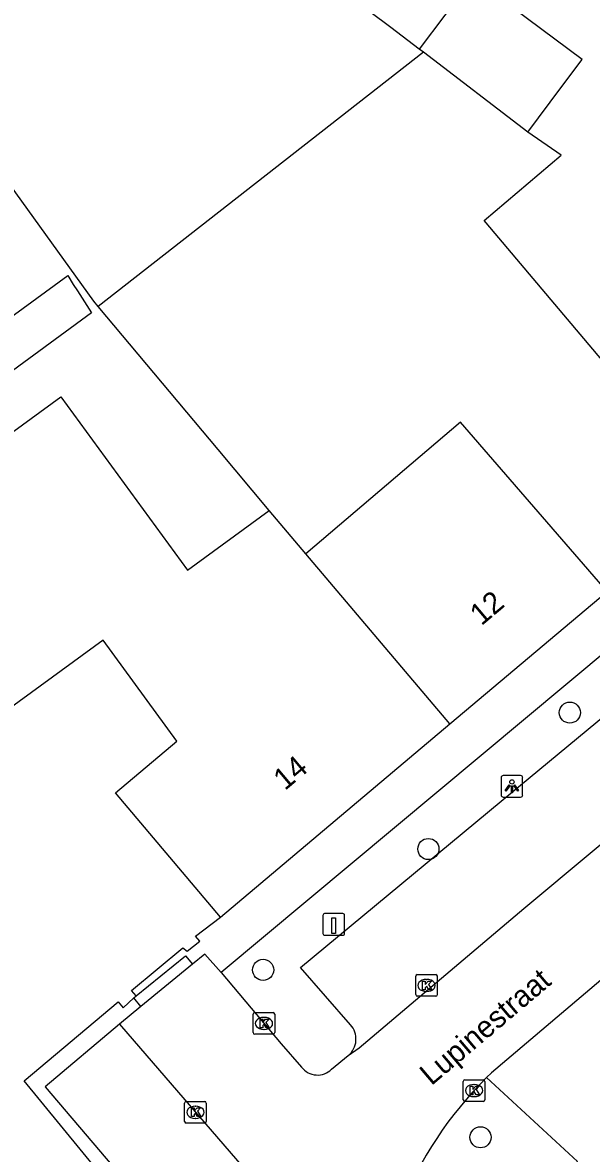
# Model space of a CAD drawing. Extents: x 161882 to 162509, y 381687 to 382379.
# Drawn here: x 162311.3 to 162337.7, y 381877.6 to 381930 of the extents above; entities that cross this region are included whole.
import ezdxf

# ---------------------------------------------------------------- set-up
doc = ezdxf.new("R2010")
doc.units = 0
for name, color, linetype in [('IMGEO_Boom', 7, 'Continuous'), ('IMGEO_Kolk', 7, 'Continuous'), ('IMGEO_Laadpaal', 7, 'Continuous'), ('IMGEO_Lichtpunt', 7, 'Continuous'), ('IMGEO_Openbare_ruimte_label', 7, 'Continuous'), ('IMGEO_Pand', 7, 'Continuous'), ('IMGEO_Pand_nummerreeks', 7, 'Continuous'), ('IMGEO_Parkeervlak_open', 7, 'Continuous'), ('IMGEO_Rijbaan_lokaal_open', 7, 'Continuous'), ('IMGEO_Voetpad_open', 7, 'Continuous')]:
    doc.layers.add(name, color=color, linetype=linetype)

msp = doc.modelspace()

# ---------------------------------------------------------------- linework, layer by layer
at = {"layer": 'IMGEO_Boom'}
for centre in [(162336.672, 381898.043), (162330.128, 381891.725), (162322.477, 381886.132), (162332.539, 381878.382)]:
    msp.add_circle(centre, 0.489, dxfattribs=at)
at = {"layer": 'IMGEO_Kolk'}
for p, q in [((162329.539, 381884.985), (162329.539, 381885.837)), ((162329.614, 381885.911), (162330.466, 381885.911)), ((162330.027, 381885.691), (162330.052, 381885.691)), ((162330.54, 381885.837), (162330.54, 381884.985)), ((162330.05, 381885.131), (162330.025, 381885.131)), ((162330.466, 381884.911), (162329.614, 381884.911)), ((162322.017, 381883.228), (162322.017, 381884.08)), ((162322.092, 381884.154), (162322.944, 381884.154)), ((162323.018, 381884.08), (162323.018, 381883.228)), ((162322.505, 381883.934), (162322.53, 381883.934)), ((162322.944, 381883.154), (162322.092, 381883.154)), ((162322.528, 381883.374), (162322.503, 381883.374)), ((162331.742, 381880.119), (162331.742, 381880.971)), ((162331.817, 381881.045), (162332.669, 381881.045)), ((162332.23, 381880.825), (162332.255, 381880.825)), ((162332.743, 381880.971), (162332.743, 381880.119)), ((162318.846, 381879.113), (162318.846, 381879.965)), ((162318.921, 381880.039), (162319.773, 381880.039)), ((162319.334, 381879.819), (162319.359, 381879.819)), ((162319.847, 381879.965), (162319.847, 381879.113)), ((162332.669, 381880.045), (162331.817, 381880.045)), ((162332.253, 381880.265), (162332.228, 381880.265)), ((162319.357, 381879.259), (162319.332, 381879.259)), ((162319.773, 381879.039), (162318.921, 381879.039))]:
    msp.add_line(p, q, dxfattribs=at)
for points in [[(162329.539, 381884.985), (162329.539, 381885.837)], [(162329.614, 381885.911), (162330.466, 381885.911)], [(162329.86, 381885.611), (162329.983, 381885.611), (162329.983, 381885.46), (162330.113, 381885.611), (162330.277, 381885.611), (162330.131, 381885.46), (162330.284, 381885.211), (162330.132, 381885.211), (162330.047, 381885.375), (162329.983, 381885.308), (162329.983, 381885.211), (162329.86, 381885.211), (162329.86, 381885.611)], [(162330.54, 381885.837), (162330.54, 381884.985)], [(162330.466, 381884.911), (162329.614, 381884.911)], [(162322.017, 381883.228), (162322.017, 381884.08)], [(162322.092, 381884.154), (162322.944, 381884.154)], [(162323.018, 381884.08), (162323.018, 381883.228)], [(162322.338, 381883.854), (162322.461, 381883.854), (162322.461, 381883.703), (162322.591, 381883.854), (162322.755, 381883.854), (162322.609, 381883.703), (162322.762, 381883.454), (162322.61, 381883.454), (162322.525, 381883.618), (162322.461, 381883.551), (162322.461, 381883.454), (162322.338, 381883.454), (162322.338, 381883.854)], [(162322.944, 381883.154), (162322.092, 381883.154)], [(162331.742, 381880.119), (162331.742, 381880.971)], [(162331.817, 381881.045), (162332.669, 381881.045)], [(162332.743, 381880.971), (162332.743, 381880.119)], [(162332.063, 381880.745), (162332.186, 381880.745), (162332.186, 381880.594), (162332.316, 381880.745), (162332.48, 381880.745), (162332.334, 381880.594), (162332.487, 381880.345), (162332.335, 381880.345), (162332.25, 381880.509), (162332.186, 381880.442), (162332.186, 381880.345), (162332.063, 381880.345), (162332.063, 381880.745)], [(162318.846, 381879.113), (162318.846, 381879.965)], [(162318.921, 381880.039), (162319.773, 381880.039)], [(162319.847, 381879.965), (162319.847, 381879.113)], [(162332.669, 381880.045), (162331.817, 381880.045)], [(162319.167, 381879.739), (162319.29, 381879.739), (162319.29, 381879.588), (162319.42, 381879.739), (162319.584, 381879.739), (162319.438, 381879.588), (162319.591, 381879.339), (162319.439, 381879.339), (162319.354, 381879.503), (162319.29, 381879.436), (162319.29, 381879.339), (162319.167, 381879.339), (162319.167, 381879.739)], [(162319.773, 381879.039), (162318.921, 381879.039)]]:
    msp.add_lwpolyline(points, dxfattribs=at)
for centre, start, end in [((162329.616, 381885.835), 91.552, 178.448), ((162329.616, 381885.835), 91.552, 178.448), ((162330.464, 381885.835), 1.552, 88.448), ((162330.464, 381885.835), 1.552, 88.448), ((162329.616, 381884.987), 181.552, 268.448), ((162329.616, 381884.987), 181.552, 268.448), ((162330.464, 381884.987), 271.552, 358.448), ((162330.464, 381884.987), 271.552, 358.448), ((162322.094, 381884.078), 91.552, 178.448), ((162322.094, 381884.078), 91.552, 178.448), ((162322.942, 381884.078), 1.552, 88.448), ((162322.942, 381884.078), 1.552, 88.448), ((162322.094, 381883.23), 181.552, 268.448), ((162322.094, 381883.23), 181.552, 268.448), ((162322.942, 381883.23), 271.552, 358.448), ((162322.942, 381883.23), 271.552, 358.448), ((162331.819, 381880.969), 91.552, 178.448), ((162331.819, 381880.969), 91.552, 178.448), ((162332.667, 381880.969), 1.552, 88.448), ((162332.667, 381880.969), 1.552, 88.448), ((162318.923, 381879.963), 91.552, 178.448), ((162318.923, 381879.963), 91.552, 178.448), ((162319.771, 381879.963), 1.552, 88.448), ((162319.771, 381879.963), 1.552, 88.448), ((162331.819, 381880.121), 181.552, 268.448), ((162331.819, 381880.121), 181.552, 268.448), ((162332.667, 381880.121), 271.552, 358.448), ((162332.667, 381880.121), 271.552, 358.448), ((162318.923, 381879.115), 181.552, 268.448), ((162318.923, 381879.115), 181.552, 268.448), ((162319.771, 381879.115), 271.552, 358.448), ((162319.771, 381879.115), 271.552, 358.448)]:
    msp.add_arc(centre, 0.0765, start, end, dxfattribs=at)
for centre, major_axis, ratio, start_param, end_param in [((162330.026, 381885.411), (-0.387, 0.002), 0.722429, 4.712389, 7.853982), ((162330.051, 381885.411), (-0.39, 0.002), 0.717154, 1.570796, 4.712389), ((162322.504, 381883.654), (-0.387, 0.002), 0.722429, 4.712389, 7.853982), ((162322.529, 381883.654), (-0.39, 0.002), 0.717154, 1.570796, 4.712389), ((162332.229, 381880.545), (-0.387, 0.002), 0.722429, 4.712389, 7.853982), ((162332.254, 381880.545), (-0.39, 0.002), 0.717154, 1.570796, 4.712389), ((162319.333, 381879.539), (-0.387, 0.002), 0.722429, 4.712389, 7.853982), ((162319.358, 381879.539), (-0.39, 0.002), 0.717154, 1.570796, 4.712389)]:
    msp.add_ellipse(centre, major_axis=major_axis, ratio=ratio, start_param=start_param, end_param=end_param, dxfattribs=at)
at = {"layer": 'IMGEO_Laadpaal'}
for p, q in [((162326.164, 381888.735), (162325.323, 381888.735)), ((162326.164, 381888.735), (162325.323, 381888.735)), ((162326.248, 381887.819), (162326.248, 381888.66)), ((162326.248, 381887.819), (162326.248, 381888.66)), ((162325.248, 381888.651), (162325.248, 381887.81)), ((162325.248, 381888.651), (162325.248, 381887.81)), ((162325.332, 381887.735), (162326.173, 381887.735)), ((162325.332, 381887.735), (162326.173, 381887.735))]:
    msp.add_line(p, q, dxfattribs=at)
msp.add_lwpolyline([(162325.663, 381888.548), (162325.823, 381888.548), (162325.823, 381887.815), (162325.663, 381887.815), (162325.663, 381888.548)], dxfattribs=at)
for centre, start, end in [((162325.326, 381888.657), 92.4484, 184.2845), ((162325.326, 381888.657), 92.4484, 184.2845), ((162326.17, 381888.657), 2.4484, 94.2845), ((162326.17, 381888.657), 2.4484, 94.2845), ((162325.326, 381887.813), 182.4484, 274.2845), ((162325.326, 381887.813), 182.4484, 274.2845), ((162326.17, 381887.813), 272.4484, 4.2845), ((162326.17, 381887.813), 272.4484, 4.2845)]:
    msp.add_arc(centre, 0.0779, start, end, dxfattribs=at)
at = {"layer": 'IMGEO_Lichtpunt'}
for p, q in [((162333.493, 381895.033), (162333.493, 381894.226)), ((162333.493, 381895.033), (162333.493, 381894.226)), ((162334.395, 381895.128), (162333.587, 381895.128)), ((162334.395, 381895.128), (162333.587, 381895.128)), ((162334.489, 381894.226), (162334.489, 381895.033)), ((162334.489, 381894.226), (162334.489, 381895.033)), ((162333.587, 381894.132), (162334.395, 381894.132)), ((162333.587, 381894.132), (162334.395, 381894.132))]:
    msp.add_line(p, q, dxfattribs=at)
for points in [[(162333.867, 381894.697), (162333.906, 381894.669), (162333.718, 381894.407), (162333.68, 381894.434), (162333.867, 381894.697)], [(162333.969, 381894.649), (162334.016, 381894.649), (162334.016, 381894.327), (162333.969, 381894.327), (162333.969, 381894.649)], [(162334.079, 381894.669), (162334.117, 381894.696), (162334.304, 381894.434), (162334.265, 381894.406), (162334.079, 381894.669)]]:
    msp.add_lwpolyline(points, dxfattribs=at)
msp.add_circle((162333.992, 381894.831), 0.0994, dxfattribs=at)
for centre, start, end in [((162333.587, 381895.033), 90, 180), ((162333.587, 381895.033), 90, 180), ((162334.395, 381895.033), 0, 90), ((162334.395, 381895.033), 0, 90), ((162333.587, 381894.226), 180, 270), ((162333.587, 381894.226), 180, 270), ((162334.395, 381894.226), 270, 0), ((162334.395, 381894.226), 270, 360)]:
    msp.add_arc(centre, 0.0946, start, end, dxfattribs=at)
at = {"layer": 'IMGEO_Pand'}
for points in [[(162329.705, 381928.752), (162328.389, 381929.759), (162322.559, 381934.122), (162315.708, 381939.25), (162314.837, 381938.086), (162316.301, 381936.99), (162316.88, 381936.187), (162312.352, 381932.924)], [(162334.722, 381924.911), (162336.256, 381926.959), (162337.238, 381928.272), (162332.18, 381932.056), (162330.883, 381930.326), (162329.705, 381928.752)], [(162329.893, 381928.608), (162314.839, 381916.848)], [(162329.893, 381928.608), (162329.705, 381928.752)], [(162334.722, 381924.911), (162329.893, 381928.608)], [(162314.839, 381916.848), (162314.64, 381917.085), (162309.637, 381924.029), (162306.732, 381928.061)], [(162343.439, 381908.114), (162340.325, 381911.802), (162332.799, 381920.714), (162332.702, 381920.828), (162336.276, 381923.854), (162334.722, 381924.911)], [(162307.853, 381914.196), (162313.435, 381918.272), (162313.691, 381917.867), (162313.882, 381917.565), (162314.529, 381916.542), (162308.947, 381912.466)], [(162322.762, 381907.393), (162320.397, 381910.215), (162314.839, 381916.848)], [(162320.508, 381888.575), (162315.645, 381894.334), (162318.477, 381896.725), (162315.068, 381901.394), (162281.55, 381876.921), (162275.507, 381885.197), (162313.123, 381912.663), (162318.985, 381904.635), (162322.762, 381907.393)], [(162338.405, 381903.648), (162331.614, 381911.491), (162324.457, 381905.392)], [(162324.457, 381905.392), (162322.762, 381907.393)], [(162331.126, 381897.517), (162324.457, 381905.392)], [(162331.126, 381897.517), (162338.405, 381903.648)], [(162320.508, 381888.575), (162331.126, 381897.517)]]:
    msp.add_lwpolyline(points, dxfattribs=at)
at = {"layer": 'IMGEO_Parkeervlak_open'}
msp.add_lwpolyline([(162326.524, 381883.594), (162324.21, 381886.239), (162333.494, 381893.939), (162344.935, 381903.424), (162347.83, 381900.027)], dxfattribs=at)
msp.add_arc((162325.773, 381882.929), 1.003, 310.2502, 41.5159, dxfattribs=at)
at = {"layer": 'IMGEO_Rijbaan_lokaal_open'}
for points in [[(162326.421, 381882.163), (162326.917, 381882.526), (162334.545, 381888.97), (162343.935, 381896.807), (162347.83, 381900.027)], [(162320.529, 381886.009), (162319.784, 381886.866), (162319.203, 381886.39)], [(162319.203, 381886.39), (162316.82, 381884.434)], [(162320.529, 381886.009), (162323.31, 381882.715), (162324.26, 381881.623)], [(162338.101, 381885.656), (162333.045, 381881.362), (162332.821, 381881.145)], [(162316.82, 381884.434), (162315.826, 381883.619)], [(162315.826, 381883.619), (162322.758, 381875.589)], [(162325.647, 381881.529), (162326.421, 381882.163)]]:
    msp.add_lwpolyline(points, dxfattribs=at)
for centre, radius, start, end in [((162324.996, 381882.2), 0.935, 218.1127, 314.133), ((162345.092, 381868.706), 17.473, 134.6115, 158.5177)]:
    msp.add_arc(centre, radius, start, end, dxfattribs=at)
at = {"layer": 'IMGEO_Voetpad_open'}
for points in [[(162348.241, 381901.811), (162344.595, 381906.095), (162320.529, 381886.009)], [(162316.601, 381884.938), (162316.382, 381885.179), (162318.764, 381887.154), (162318.965, 381886.995), (162319.543, 381887.466), (162319.343, 381887.695), (162320.508, 381888.575)], [(162316.601, 381884.938), (162318.886, 381886.776), (162319.203, 381886.39)], [(162308.695, 381857.661), (162317.651, 381867.68), (162320.093, 381870.515), (162317.508, 381873.557), (162311.416, 381880.988), (162315.774, 381884.648), (162315.994, 381884.379), (162316.488, 381884.836)], [(162316.488, 381884.836), (162316.601, 381884.938)], [(162316.82, 381884.434), (162316.488, 381884.836)], [(162315.826, 381883.619), (162312.385, 381880.712), (162318.649, 381873.357)], [(162332.821, 381881.145), (162337.02, 381877.264), (162327.942, 381867.176), (162325.146, 381864.385), (162324.203, 381865.309)]]:
    msp.add_lwpolyline(points, dxfattribs=at)

# ---------------------------------------------------------------- texts
at = {"layer": 'IMGEO_Openbare_ruimte_label'}
msp.add_text('Lupinestraat', height=1, rotation=40.2969, dxfattribs=at).set_placement((162330.262, 381880.745))
at = {"layer": 'IMGEO_Pand_nummerreeks'}
for s, rotation, p in [('12', 40.107, (162332.578, 381902.035)), ('14', 40.0784, (162323.485, 381894.407))]:
    msp.add_text(s, height=1, rotation=rotation, dxfattribs=at).set_placement(p)

doc.saveas('drawing.dxf')
